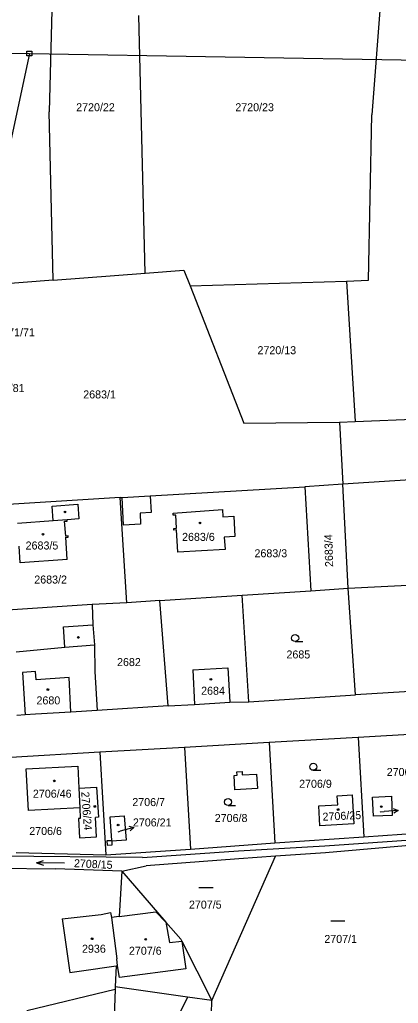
# Model space of a CAD drawing. Extents: x -755819 to -753140, y -1169796 to -1166000.
# Drawn here: x -754219.3 to -754138.8, y -1168719.7 to -1168510.8 of the extents above; entities that cross this region are included whole.
import ezdxf

# ---------------------------------------------------------------- set-up
doc = ezdxf.new("R2010")
doc.units = 0
for name, color, linetype in [('Vrstva 1', 7, 'Continuous'), ('Vrstva 12', 7, 'Continuous'), ('Vrstva 16', 7, 'Continuous'), ('Vrstva 18', 7, 'Continuous'), ('Vrstva 19', 7, 'Continuous'), ('Vrstva 25', 7, 'Continuous'), ('Vrstva 26', 7, 'Continuous'), ('Vrstva 4', 7, 'Continuous'), ('Vrstva 6', 7, 'Continuous')]:
    doc.layers.add(name, color=color, linetype=linetype)

msp = doc.modelspace()

# ---------------------------------------------------------------- linework, layer by layer
at = {"layer": 'Vrstva 1'}
for p, q in [((-754211.95, -1168486.6), (-754213.02, -1168530.41)), ((-754212.17, -1168566.12), (-754192.65, -1168564.62)), ((-754192.65, -1168564.62), (-754184.41, -1168563.98)), ((-754184.41, -1168563.98), (-754183.09, -1168567.34)), ((-754212.17, -1168566.12), (-754233.27, -1168567.76)), ((-754183.09, -1168567.34), (-754171.66, -1168596.49)), ((-754171.66, -1168596.49), (-754151.31, -1168596.27)), ((-754151.31, -1168596.27), (-754147.99, -1168596.13)), ((-754151.31, -1168596.27), (-754150.61, -1168609.44)), ((-754147.99, -1168596.13), (-754121.29, -1168595.04)), ((-754123.83, -1168607.71), (-754150.61, -1168609.44)), ((-754191.59, -1168611.95), (-754158.65, -1168610.01)), ((-754150.61, -1168609.44), (-754158.65, -1168610.01)), ((-754158.65, -1168610.01), (-754157.4, -1168632.09)), ((-754149.44, -1168631.58), (-754150.61, -1168609.44)), ((-754197.95, -1168612.32), (-754230.8, -1168614.31)), ((-754197.95, -1168612.32), (-754197.54, -1168612.26)), ((-754196.55, -1168634.65), (-754197.95, -1168612.32)), ((-754197.54, -1168612.26), (-754191.59, -1168611.95)), ((-754212.44, -1168614.11), (-754206.98, -1168613.7)), ((-754212.21, -1168617.26), (-754212.44, -1168614.11)), ((-754206.98, -1168613.7), (-754206.74, -1168616.85)), ((-754186.71, -1168615.59), (-754176.19, -1168614.87)), ((-754176.19, -1168614.87), (-754176.1, -1168616.4)), ((-754212.21, -1168617.26), (-754219.78, -1168617.82)), ((-754209.76, -1168617.33), (-754209.21, -1168617.29)), ((-754209.54, -1168620.48), (-754209.76, -1168617.33)), ((-754206.74, -1168616.85), (-754209.23, -1168617.04)), ((-754209.21, -1168617.29), (-754209.23, -1168617.04)), ((-754186.69, -1168616.07), (-754186.71, -1168615.59)), ((-754186.12, -1168616.04), (-754186.69, -1168616.07)), ((-754185.98, -1168618.83), (-754186.12, -1168616.04)), ((-754176.1, -1168616.4), (-754173.79, -1168616.25)), ((-754173.79, -1168616.25), (-754173.56, -1168620.57)), ((-754186.55, -1168618.86), (-754185.98, -1168618.83)), ((-754186.53, -1168619.22), (-754186.55, -1168618.86)), ((-754185.96, -1168619.19), (-754186.53, -1168619.22)), ((-754185.71, -1168623.94), (-754185.96, -1168619.19)), ((-754208.99, -1168620.44), (-754209.54, -1168620.48)), ((-754209.52, -1168620.73), (-754208.98, -1168620.69)), ((-754209.2, -1168625.48), (-754209.52, -1168620.73)), ((-754208.98, -1168620.69), (-754208.99, -1168620.44)), ((-754173.56, -1168620.57), (-754175.82, -1168620.72)), ((-754175.82, -1168620.72), (-754175.66, -1168623.31)), ((-754219.2, -1168626.16), (-754219.44, -1168622.63)), ((-754175.66, -1168623.31), (-754185.71, -1168623.94)), ((-754209.2, -1168625.48), (-754219.2, -1168626.16)), ((-754149.44, -1168631.58), (-754108.86, -1168629.4)), ((-754157.4, -1168632.09), (-754149.44, -1168631.58)), ((-754147.88, -1168654.2), (-754149.44, -1168631.58)), ((-754189.54, -1168634.17), (-754172, -1168633.04)), ((-754172, -1168633.04), (-754157.4, -1168632.09)), ((-754170.58, -1168655.72), (-754172, -1168633.04)), ((-754203.91, -1168635.03), (-754243.94, -1168637.72)), ((-754196.55, -1168634.65), (-754203.91, -1168635.03)), ((-754203.91, -1168635.03), (-754203.74, -1168639.33)), ((-754189.54, -1168634.17), (-754196.55, -1168634.65)), ((-754187.77, -1168656.58), (-754189.54, -1168634.17)), ((-754210.01, -1168639.76), (-754203.74, -1168639.33)), ((-754209.74, -1168644.1), (-754210.01, -1168639.76)), ((-754203.74, -1168639.33), (-754203.44, -1168643.57)), ((-754220.05, -1168645.06), (-754209.74, -1168644.1)), ((-754203.44, -1168643.57), (-754203.31, -1168649.24)), ((-754203.31, -1168649.24), (-754202.83, -1168657.52)), ((-754121.27, -1168652.61), (-754147.88, -1168654.2)), ((-754170.58, -1168655.72), (-754147.88, -1168654.2)), ((-754187.77, -1168656.58), (-754202.83, -1168657.52)), ((-754187.77, -1168656.58), (-754182.17, -1168656.29)), ((-754182.17, -1168656.29), (-754174.64, -1168655.75)), ((-754174.64, -1168655.75), (-754170.58, -1168655.72)), ((-754218.17, -1168658.46), (-754219.96, -1168658.58)), ((-754215.94, -1168658.32), (-754218.17, -1168658.46)), ((-754208.42, -1168657.91), (-754215.94, -1168658.32)), ((-754202.83, -1168657.52), (-754208.42, -1168657.91)), ((-754147.33, -1168663.25), (-754166.3, -1168664.34)), ((-754128.37, -1168662.15), (-754147.33, -1168663.25)), ((-754147.33, -1168663.25), (-754146.12, -1168684.39)), ((-754184.28, -1168665.38), (-754202.25, -1168666.41)), ((-754166.3, -1168664.34), (-754184.28, -1168665.38)), ((-754184.28, -1168665.38), (-754183.03, -1168686.99)), ((-754166.3, -1168664.34), (-754165.07, -1168685.65)), ((-754202.25, -1168666.41), (-754221.22, -1168667.51)), ((-754202.25, -1168666.41), (-754200.98, -1168688.2)), ((-754217.92, -1168669.9), (-754206.97, -1168669.34)), ((-754206.97, -1168669.34), (-754206.75, -1168674.02)), ((-754217.45, -1168678.8), (-754217.92, -1168669.9)), ((-754206.75, -1168674.02), (-754202.98, -1168673.85)), ((-754206.75, -1168674.02), (-754206.56, -1168678.22)), ((-754202.98, -1168673.85), (-754202.54, -1168680.21)), ((-754151.8, -1168675.66), (-754148.6, -1168675.48)), ((-754151.69, -1168677.58), (-754151.8, -1168675.66)), ((-754148.6, -1168675.48), (-754148.25, -1168681.59)), ((-754144.29, -1168675.93), (-754140.27, -1168675.76)), ((-754140.27, -1168675.76), (-754140.08, -1168679.86)), ((-754155.74, -1168677.81), (-754151.69, -1168677.58)), ((-754155.5, -1168682), (-754155.74, -1168677.81)), ((-754144.09, -1168679.96), (-754144.29, -1168675.93)), ((-754206.56, -1168678.22), (-754217.45, -1168678.8)), ((-754206.56, -1168678.22), (-754206.46, -1168680.45)), ((-754200.1, -1168680.12), (-754197.1, -1168679.94)), ((-754197.1, -1168679.94), (-754196.66, -1168685.06)), ((-754140.08, -1168679.86), (-754144.09, -1168679.96)), ((-754206.46, -1168680.45), (-754206.83, -1168680.47)), ((-754206.83, -1168680.47), (-754206.58, -1168684.55)), ((-754202.54, -1168680.21), (-754203.2, -1168680.25)), ((-754202.96, -1168684.34), (-754203.2, -1168680.25)), ((-754199.76, -1168685.12), (-754200.1, -1168680.12)), ((-754148.25, -1168681.59), (-754155.5, -1168682)), ((-754146.12, -1168684.39), (-754127.17, -1168683)), ((-754206.58, -1168684.55), (-754202.96, -1168684.34)), ((-754200.69, -1168685.18), (-754199.76, -1168685.12)), ((-754200.64, -1168686.18), (-754200.69, -1168685.18)), ((-754199.74, -1168686.12), (-754200.64, -1168686.18)), ((-754196.66, -1168685.06), (-754199.75, -1168685.27)), ((-754199.75, -1168685.27), (-754199.74, -1168686.12)), ((-754183.03, -1168686.99), (-754165.07, -1168685.65)), ((-754165.07, -1168685.65), (-754146.12, -1168684.39)), ((-754154.43, -1168686.3), (-754131.19, -1168684.7)), ((-754130.98, -1168685.76), (-754154.32, -1168687.8)), ((-754193.21, -1168688.76), (-754241.04, -1168688.28)), ((-754220.05, -1168687.72), (-754200.98, -1168688.2)), ((-754200.98, -1168688.2), (-754183.03, -1168686.99)), ((-754193.21, -1168688.76), (-754172.79, -1168687.32)), ((-754172.79, -1168687.32), (-754154.43, -1168686.3)), ((-754154.32, -1168687.8), (-754164.91, -1168688.5)), ((-754172.69, -1168689.01), (-754192.44, -1168690.5)), ((-754178.46, -1168719.16), (-754164.91, -1168688.5)), ((-754164.91, -1168688.5), (-754172.69, -1168689.01)), ((-754224.05, -1168691.06), (-754211.68, -1168691.19)), ((-754197.57, -1168691.66), (-754211.68, -1168691.19)), ((-754197.57, -1168691.66), (-754198.15, -1168701.31)), ((-754197.57, -1168691.66), (-754192.44, -1168690.5)), ((-754197.57, -1168691.66), (-754188.23, -1168702.47)), ((-754210.31, -1168701.81), (-754202.02, -1168700.87)), ((-754202.02, -1168700.87), (-754199.99, -1168700.41)), ((-754199.99, -1168700.41), (-754199.79, -1168701.53)), ((-754210.31, -1168701.81), (-754208.69, -1168713.19)), ((-754198.15, -1168701.31), (-754199.79, -1168701.53)), ((-754199.79, -1168701.53), (-754198.68, -1168710.29)), ((-754188.23, -1168702.47), (-754185.06, -1168706.14)), ((-754185.06, -1168706.14), (-754184.87, -1168706.51)), ((-754184.87, -1168706.51), (-754178.46, -1168719.16)), ((-754198.5, -1168711.75), (-754198.68, -1168710.29)), ((-754208.69, -1168713.19), (-754206.21, -1168712.84)), ((-754206.21, -1168712.84), (-754198.77, -1168711.79)), ((-754198.77, -1168711.79), (-754199.04, -1168716.24)), ((-754198.77, -1168711.79), (-754198.5, -1168711.75)), ((-754199.02, -1168716.79), (-754217.79, -1168721.36)), ((-754199.02, -1168716.79), (-754199.54, -1168729.59)), ((-754199.04, -1168716.24), (-754199.02, -1168716.79)), ((-754183.6, -1168718.43), (-754199.04, -1168716.24)), ((-754178.46, -1168719.16), (-754183.6, -1168718.43)), ((-754178.5, -1168721.98), (-754178.46, -1168719.16))]:
    msp.add_line(p, q, dxfattribs=at)
at = {"layer": 'Vrstva 12'}
for p, q in [((-754425.6, -1168514.36), (-754217.27, -1168518)), ((-754217.27, -1168518), (-754227.92, -1168567.1)), ((-754217.27, -1168518), (-754029.1, -1168521.22))]:
    msp.add_line(p, q, dxfattribs=at)
at = {"layer": 'Vrstva 16'}
for p, q in [((-754142.64, -1168679.06), (-754141.82, -1168679)), ((-754138.83, -1168678.76), (-754141.82, -1168679)), ((-754198.41, -1168683.28), (-754197.92, -1168683.15)), ((-754195.03, -1168682.36), (-754197.92, -1168683.15))]:
    msp.add_line(p, q, dxfattribs=at)
for points in [[(-754139.87, -1168678.34), (-754138.83, -1168678.76), (-754139.79, -1168679.34)], [(-754196.12, -1168682.14), (-754195.03, -1168682.36), (-754195.86, -1168683.1)]]:
    msp.add_lwpolyline(points, dxfattribs=at)
at = {"layer": 'Vrstva 25'}
for p, q in [((-754160.74, -1168642.9), (-754159.14, -1168642.9)), ((-754156.89, -1168670.24), (-754155.29, -1168670.24)), ((-754175.01, -1168677.73), (-754173.41, -1168677.73)), ((-754181.2, -1168695.16), (-754178.2, -1168695.16)), ((-754153.17, -1168702.18), (-754150.17, -1168702.18))]:
    msp.add_line(p, q, dxfattribs=at)
for points in [[(-754215.76, -1168689.86), (-754214.25, -1168689.38)], [(-754209.76, -1168689.94), (-754215.76, -1168689.86), (-754214.27, -1168690.38)]]:
    msp.add_lwpolyline(points, dxfattribs=at)
for centre, radius in [((-754209.69, -1168615.37), 0.175), ((-754180.98, -1168617.71), 0.175), ((-754214.37, -1168620.09), 0.175), ((-754206.84, -1168642.02), 0.175), ((-754160.74, -1168642.15), 0.75), ((-754178.66, -1168650.93), 0.175), ((-754213.32, -1168653.09), 0.175), ((-754156.89, -1168669.49), 0.75), ((-754211.96, -1168672.48), 0.175), ((-754203.34, -1168677.92), 0.175), ((-754175.01, -1168676.98), 0.75), ((-754142.43, -1168677.96), 0.175), ((-754151.61, -1168678.57), 0.175), ((-754198.39, -1168681.86), 0.175), ((-754203.92, -1168706.03), 0.175), ((-754192.52, -1168706.14), 0.175)]:
    msp.add_circle(centre, radius, dxfattribs=at)
at = {"layer": 'Vrstva 26'}
msp.add_lwpolyline([(-754217.77, -1168517.5), (-754216.77, -1168517.5), (-754216.77, -1168518.5), (-754217.77, -1168518.5)], close=True, dxfattribs=at)
at = {"layer": 'Vrstva 4'}
for p, q in [((-754197.22, -1168618.19), (-754197.54, -1168612.26)), ((-754191.59, -1168611.95), (-754191.38, -1168615.47)), ((-754209.23, -1168617.04), (-754212.21, -1168617.26)), ((-754191.38, -1168615.47), (-754193.73, -1168615.61)), ((-754193.73, -1168615.61), (-754193.6, -1168617.99)), ((-754193.6, -1168617.99), (-754197.22, -1168618.19)), ((-754209.74, -1168644.1), (-754203.44, -1168643.57)), ((-754182.52, -1168648.89), (-754175.05, -1168648.44)), ((-754175.05, -1168648.44), (-754174.64, -1168655.75)), ((-754215.96, -1168649.27), (-754218.69, -1168649.43)), ((-754218.69, -1168649.43), (-754218.17, -1168658.46)), ((-754215.84, -1168651.02), (-754215.96, -1168649.27)), ((-754208.83, -1168650.5), (-754215.84, -1168651.02)), ((-754208.42, -1168657.91), (-754208.83, -1168650.5)), ((-754182.52, -1168648.89), (-754182.17, -1168656.29)), ((-754173.74, -1168671.31), (-754173.09, -1168671.27)), ((-754173.55, -1168674.39), (-754173.74, -1168671.31)), ((-754173.13, -1168670.57), (-754172.02, -1168670.51)), ((-754173.09, -1168671.27), (-754173.13, -1168670.57)), ((-754172.02, -1168670.51), (-754171.98, -1168671.21)), ((-754171.98, -1168671.21), (-754168.95, -1168671.03)), ((-754168.95, -1168671.03), (-754168.77, -1168674.11)), ((-754168.77, -1168674.11), (-754173.55, -1168674.39)), ((-754198.15, -1168701.31), (-754190.37, -1168700.27)), ((-754190.37, -1168700.27), (-754188.23, -1168702.47)), ((-754188.23, -1168702.47), (-754187.48, -1168706.84)), ((-754187.48, -1168706.84), (-754184.87, -1168706.51)), ((-754184.87, -1168706.51), (-754183.99, -1168712.39)), ((-754198.11, -1168714.27), (-754198.5, -1168711.75)), ((-754183.99, -1168712.39), (-754198.11, -1168714.27))]:
    msp.add_line(p, q, dxfattribs=at)
at = {"layer": 'Vrstva 6'}
for p, q in [((-754139.34, -1168463.56), (-754144.42, -1168531.02)), ((-754192.65, -1168564.62), (-754193.99, -1168509.93)), ((-754212.17, -1168566.12), (-754213.02, -1168530.41)), ((-754145.16, -1168566.12), (-754144.42, -1168531.02)), ((-754183.09, -1168567.34), (-754149.8, -1168566.35)), ((-754149.8, -1168566.35), (-754145.16, -1168566.12)), ((-754149.8, -1168566.35), (-754147.99, -1168596.13)), ((-754183.6, -1168718.43), (-754188.92, -1168729.13))]:
    msp.add_line(p, q, dxfattribs=at)

# ---------------------------------------------------------------- texts
at = {"layer": 'Vrstva 16'}
for s, p in [('2671/71', (-754224.31, -1168578.06)), ('2671/81', (-754226.5, -1168589.9)), ('2706/21', (-754195.25, -1168682.16))]:
    msp.add_text(s, height=1.7, dxfattribs=at).set_placement(p)
at = {"layer": 'Vrstva 18'}
for s, p in [('2720/22', (-754207.31, -1168530.25)), ('2720/23', (-754173.47, -1168530.25)), ('2720/13', (-754168.75, -1168581.86)), ('2683/1', (-754205.81, -1168591.25)), ('2683/3', (-754169.39, -1168624.99)), ('2683/2', (-754216.22, -1168630.57)), ('2682', (-754198.62, -1168648.1)), ('2685', (-754162.59, -1168646.48)), ('2706/10', (-754141.27, -1168671.45)), ('2706/9', (-754159.9, -1168673.95)), ('2706/7', (-754195.37, -1168677.84)), ('2706/8', (-754177.84, -1168681.22)), ('2706/6', (-754217.29, -1168683.98)), ('2707/5', (-754183.33, -1168699.62)), ('2707/1', (-754154.54, -1168706.91))]:
    msp.add_text(s, height=1.7, dxfattribs=at).set_placement(p)
for s, rotation, p in [('2683/4', 91.7878, (-754152.65, -1168627.03)), ('2708/15', 357.2965, (-754207.82, -1168690.8))]:
    msp.add_text(s, height=1.7, rotation=rotation, dxfattribs=at).set_placement(p)
at = {"layer": 'Vrstva 19'}
for s, height, p in [('2683/6', 1.7, (-754184.79, -1168621.51)), ('2683/5', 1.7, (-754218.06, -1168623.34)), ('2684', 1.7, (-754180.74, -1168654.19)), ('2680', 1.7, (-754215.75, -1168656.24)), ('2706/46', 1.7, (-754216.51, -1168676.06)), ('2706/32', 0.1, (-754142.94, -1168679.06)), ('2706/21', 0.1, (-754198.68, -1168683.28)), ('2936', 1.7, (-754206.07, -1168708.99)), ('2707/6', 1.7, (-754196.09, -1168709.42))]:
    msp.add_text(s, height=height, dxfattribs=at).set_placement(p)
for s, rotation, p in [('2706/24', 274.1603, (-754206.24, -1168674.84)), ('2706/25', 2.6356, (-754154.88, -1168680.96))]:
    msp.add_text(s, height=1.7, rotation=rotation, dxfattribs=at).set_placement(p)

doc.saveas('drawing.dxf')
